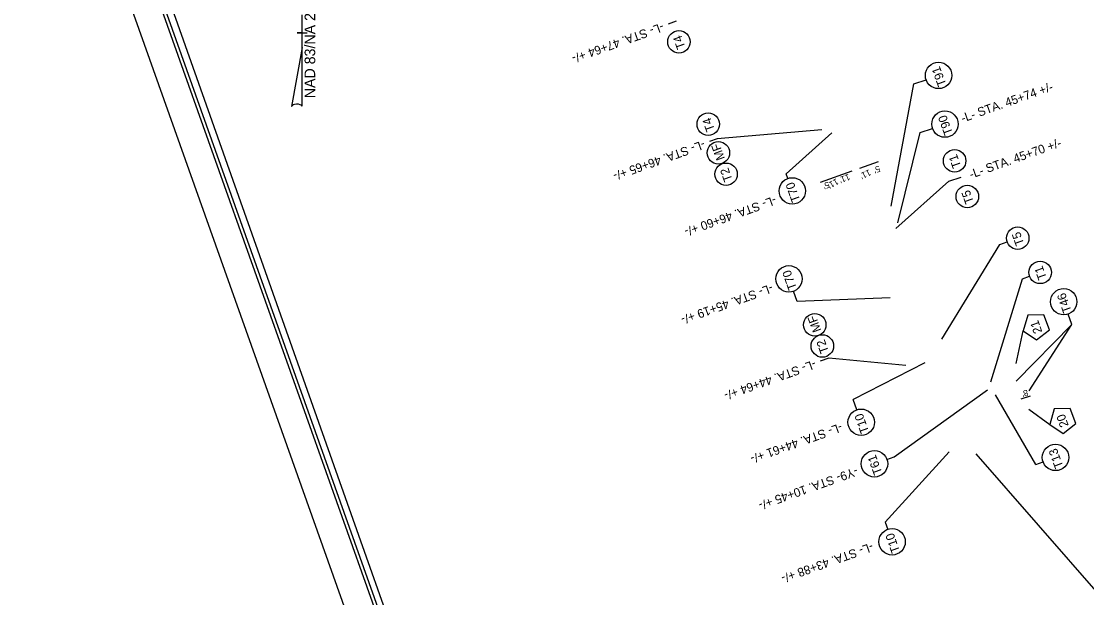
# Model space of a CAD drawing. Extents: x 1615843 to 1617934, y 901966 to 903921.
# Drawn here: x 1615843 to 1616697, y 902832 to 903293 of the extents above; entities that cross this region are included whole.
import ezdxf

# ---------------------------------------------------------------- set-up
doc = ezdxf.new("R2010")
doc.units = 0
for name, color, linetype in [('Prop Terminator CELL', 7, 'Continuous'), ('Sheet Border Standard 30in CELL', 7, 'Continuous'), ('Sheet Clip Boundary CELL', 7, 'Continuous'), ('Sheet Plot Border Inside CELL', 7, 'Continuous'), ('Sheet Plot Border Outside CELL', 7, 'Continuous'), ('Sheet Sticker Incomplete CELL', 7, 'Continuous')]:
    doc.layers.add(name, color=color, linetype=linetype)

msp = doc.modelspace()

# ---------------------------------------------------------------- linework, layer by layer
at = {"layer": 'Prop Terminator CELL'}
for p, q in [((1616067.94, 903272.46), (1616067.94, 903298.66)), ((1616063.94, 903284.06), (1616063.89, 903284.06)), ((1616067.49, 903284.06), (1616063.94, 903284.06)), ((1616063.99, 903284.06), (1616071.99, 903284.06)), ((1616067.94, 903272.46), (1616059.59, 903225.21)), ((1616067.99, 903225.41), (1616067.94, 903272.46))]:
    msp.add_line(p, q, dxfattribs=at)
msp.add_ellipse((1616063.83, 903225.05), major_axis=(4.23, -0.03), ratio=0.461098, start_param=0.201328, end_param=3.141593, dxfattribs=at)
at = {"layer": 'Sheet Border Standard 30in CELL'}
msp.add_lwpolyline([(1615872.27, 903544.74), (1616374.72, 902131.39), (1617364.06, 902483.11), (1616861.61, 903896.45)], close=True, dxfattribs=at)
at = {"layer": 'Sheet Clip Boundary CELL'}
for p, q in [((1616367.56, 903293.34), (1616361.23, 903291.09)), ((1616539.81, 903145.41), (1616558, 903243.26)), ((1616558, 903243.26), (1616567.86, 903246.46)), ((1616563.14, 903204.29), (1616573, 903207.5)), ((1616400.6, 903199.26), (1616394.27, 903197.01)), ((1616484.46, 903206.5), (1616400.6, 903199.26)), ((1616492.22, 903204.04), (1616455.81, 903171.24)), ((1616545.27, 903132.01), (1616563.14, 903204.29)), ((1616514.73, 903175.82), (1616529.66, 903181.13)), ((1616483.17, 903164.6), (1616508.61, 903173.64)), ((1616457.14, 903167.53), (1616455.81, 903171.24)), ((1616543.59, 903127.45), (1616586.14, 903165.33)), ((1616586.14, 903165.33), (1616596, 903168.53)), ((1616580.43, 903038.74), (1616627.03, 903114.63)), ((1616627.03, 903114.63), (1616632.75, 903116.66)), ((1616619.68, 903004.7), (1616645.08, 903087.28)), ((1616645.08, 903087.28), (1616650.8, 903089.32)), ((1616464.47, 903068.99), (1616461.56, 903077.19)), ((1616539.13, 903071.88), (1616464.47, 903068.99)), ((1616684.55, 903050.7), (1616681.64, 903058.89)), ((1616639.99, 903019.41), (1616645.74, 903045.62)), ((1616640.02, 903005.23), (1616684.55, 903050.7)), ((1616650.52, 902997.45), (1616684.55, 903050.7)), ((1616489.95, 903023.54), (1616483.12, 903021.11)), ((1616551.5, 903017.9), (1616489.95, 903023.54)), ((1616566.74, 903019.83), (1616509.41, 902990.51)), ((1616542.18, 902944.64), (1616617.03, 902998.34)), ((1616655.86, 902938.61), (1616623.38, 902994.29)), ((1616643.91, 902991.19), (1616651.61, 902993.37)), ((1616512.32, 902982.32), (1616509.41, 902990.51)), ((1616650.17, 902982.83), (1616666.88, 902970.63)), ((1616586.25, 902948.55), (1616535.02, 902892.37)), ((1616536.46, 902942.61), (1616542.18, 902944.64)), ((1616607.7, 902946.99), (1616707.62, 902832.86)), ((1616655.86, 902938.61), (1616661.58, 902940.64)), ((1616535.02, 902892.37), (1616537.07, 902886.6))]:
    msp.add_line(p, q, dxfattribs=at)
for points in [[(1616645.74, 903045.62), (1616656.41, 903038.36), (1616666.61, 903046.27), (1616662.25, 903058.41), (1616649.35, 903058.02)], [(1616666.88, 902970.63), (1616677.55, 902963.37), (1616687.75, 902971.27), (1616683.39, 902983.42), (1616670.49, 902983.02)]]:
    msp.add_lwpolyline(points, close=True, dxfattribs=at)
for centre, radius in [((1616369.88, 903276.97), 9.01), ((1616577.83, 903250), 10.58), ((1616393.34, 903210.98), 9.01), ((1616582.97, 903211.04), 10.58), ((1616401.44, 903188.01), 9.01), ((1616590.72, 903181.68), 9.01), ((1616407.59, 903170.89), 9.01), ((1616460.68, 903157.56), 10.58), ((1616600.88, 903153.09), 9.01), ((1616641.24, 903119.67), 9.01), ((1616458.01, 903087.15), 10.58), ((1616659.29, 903092.33), 9.01), ((1616678.09, 903068.86), 10.58), ((1616478.63, 903050.33), 9.01), ((1616484.74, 903033.39), 9.01), ((1616515.86, 902972.36), 10.58), ((1616671.55, 902944.19), 10.58), ((1616526.5, 902939.07), 10.58), ((1616540.61, 902876.63), 10.58)]:
    msp.add_circle(centre, radius, dxfattribs=at)
at = {"layer": 'Sheet Plot Border Inside CELL'}
msp.add_lwpolyline([(1615865.68, 903555.66), (1616423.91, 901985.43), (1617418.05, 902338.86), (1616859.83, 903909.09)], close=True, dxfattribs=at)
at = {"layer": 'Sheet Plot Border Outside CELL'}
msp.add_lwpolyline([(1615843.02, 903552.38), (1616407.11, 901965.67), (1617443.56, 902334.13), (1616879.47, 903920.85)], close=True, dxfattribs=at)
at = {"layer": 'Sheet Sticker Incomplete CELL'}
msp.add_lwpolyline([(1616920.55, 902382.99), (1616299.46, 902356.07), (1615953.12, 903334.31), (1616369.18, 903520.6), (1616903.33, 903759.78), (1617120.19, 903154.34), (1616822.61, 903059.96), (1617083.45, 902390.05)], close=True, dxfattribs=at)

# ---------------------------------------------------------------- texts
at = {"layer": 'Prop Terminator CELL'}
msp.add_text('NAD 83/NA 2011', height=8.5, rotation=90, dxfattribs=at).set_placement((1616078.46, 903231.75))
at = {"layer": 'Sheet Clip Boundary CELL'}
for s, height, rotation, p in [('-L- STA. 47+64 +/-', 7, 199.57069, (1616356.37, 903292.34)), ('T4', 7, 109.53987, (1616375.2, 903272.46)), ('T91', 7, 110.1663, (1616584.23, 903242.72)), ('-L- STA. 45+74 +/-', 7, 19.57069, (1616597.25, 903212.2)), ('T4', 7, 109.53987, (1616398.66, 903206.47)), ('T90', 7, 110.1663, (1616589.37, 903203.75)), ('-L- STA. 45+70 +/-', 7, 19.57069, (1616603.88, 903167.26)), ('-L- STA. 46+65 +/-', 7, 199.57069, (1616389.4, 903198.27)), ('MF', 7, 110.1663, (1616406.81, 903183.56)), ('T1', 7, 109.53987, (1616596.03, 903177.16)), ('T2', 7, 109.53987, (1616412.91, 903166.38)), ("11'", 5, 205.01851, (1616522.28, 903174.96)), ("5'", 5, 200.06724, (1616530, 903177.93)), ('T70', 7, 109.57069, (1616467.11, 903150.02)), ("5'", 5, 200.87995, (1616489.37, 903165.17)), ("11'", 5, 209.2009, (1616496, 903167.77)), ("11'", 5, 201.45444, (1616505.78, 903171.41)), ('T5', 7, 109.53987, (1616606.19, 903148.58)), ('-L- STA. 46+60 +/-', 7, 199.57069, (1616446.48, 903153.66)), ('T5', 7, 109.53987, (1616646.56, 903115.16)), ('T1', 7, 109.53987, (1616664.61, 903087.82)), ('T70', 7, 109.57069, (1616464.44, 903079.61)), ('-L- STA. 45+19 +/-', 7, 199.57069, (1616443.81, 903083.25)), ('T46', 7, 109.57069, (1616684.52, 903061.32)), ('MF', 7, 110.1663, (1616483.99, 903045.88)), ('21', 7, 109.53987, (1616661.02, 903044.71)), ('T2', 7, 109.53987, (1616490.06, 903028.88)), ('-L- STA. 44+64 +/-', 7, 199.57069, (1616478.29, 903022.45)), ("8'", 5, 197.67789, (1616648.7, 902998.67)), ('T10', 7, 109.57069, (1616522.3, 902964.82)), ('20', 7, 109.53987, (1616682.16, 902969.71)), ('-L- STA. 44+61 +/-', 7, 199.57069, (1616499.38, 902971.85)), ('T13', 7, 110.1663, (1616677.96, 902936.9)), ('T61', 7, 110.1663, (1616532.9, 902931.78)), ('-Y9- STA. 10+45 +/-', 7, 199.57069, (1616511.88, 902936.67)), ('T10', 7, 109.57069, (1616547.05, 902869.09)), ('-L- STA. 43+88 +/-', 7, 199.57069, (1616524.13, 902876.13))]:
    msp.add_text(s, height=height, rotation=rotation, dxfattribs=at).set_placement(p)

doc.saveas('drawing.dxf')
